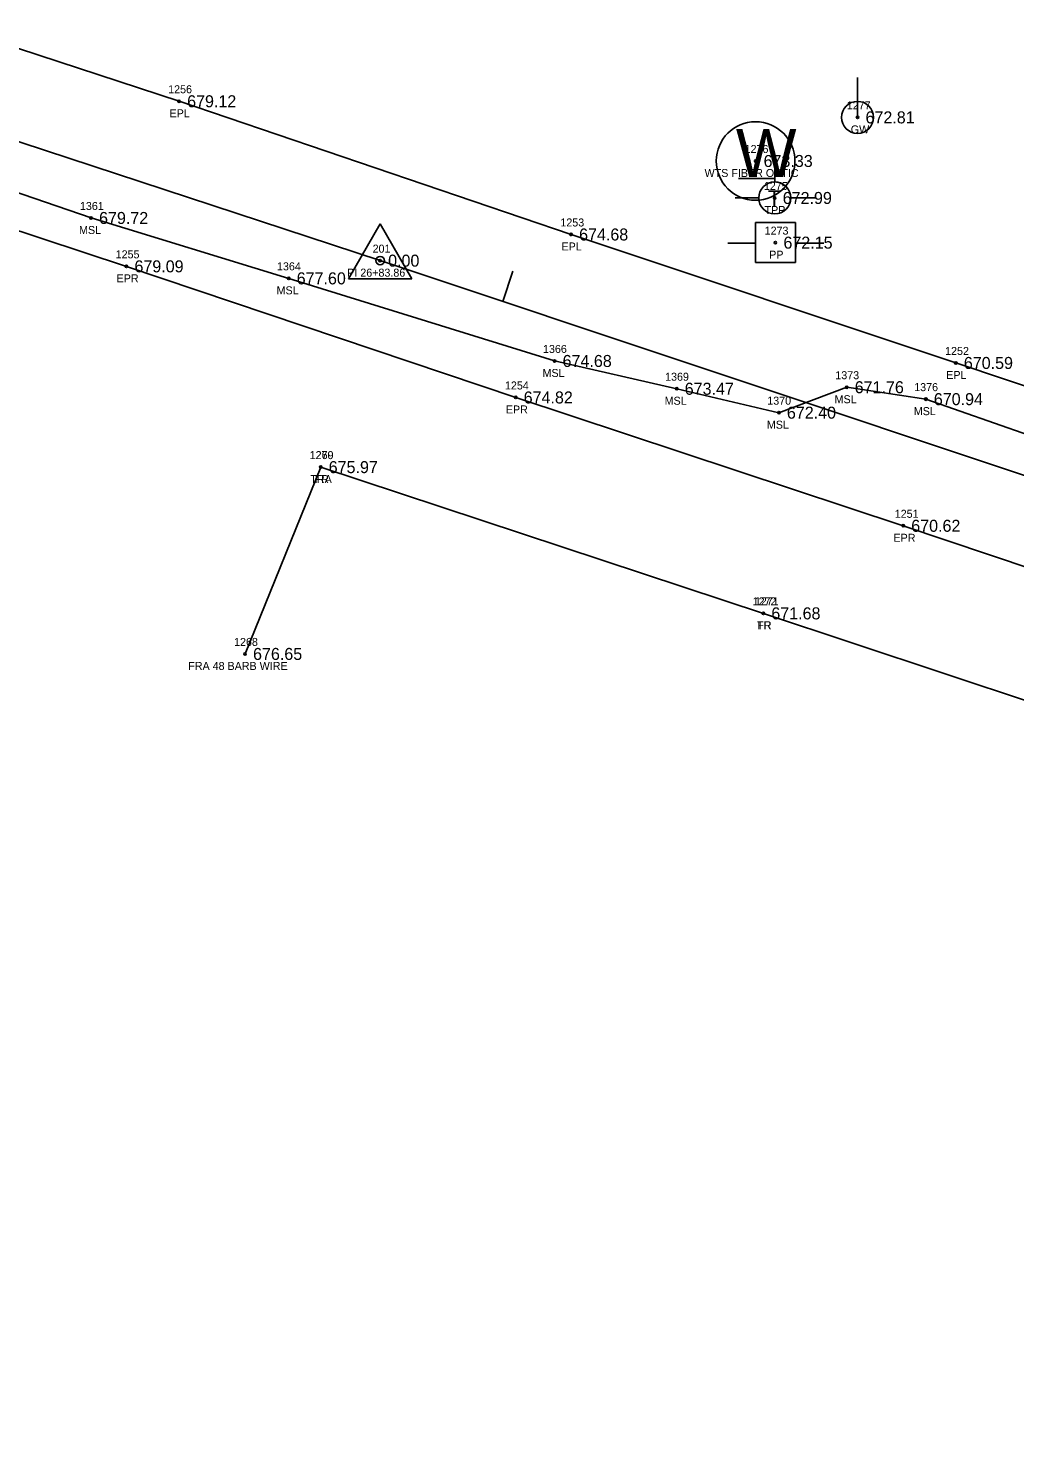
# Model space of a CAD drawing. Extents: x 1655137 to 1657928, y 1003994 to 1005407.
# Drawn here: x 1656025.3 to 1656148.5, y 1004580.8 to 1004755.9 of the extents above; entities that cross this region are included whole.
import ezdxf

# ---------------------------------------------------------------- set-up
doc = ezdxf.new("R2010")
doc.units = 0
for name, color, linetype in [('RD_EX_Fence_Other', 7, 'Continuous'), ('RD_EX_Fence_Other_txCode', 7, 'Continuous'), ('RD_EX_Misc', 7, 'Continuous'), ('RD_EX_Misc_txCode', 7, 'Continuous'), ('RD_EX_Road', 7, 'Continuous'), ('RD_EX_Road_txCode', 7, 'Continuous'), ('RD_EX_TX_Fence_Other_ELEV', 7, 'Continuous'), ('RD_EX_TX_Misc_ELEV', 7, 'Continuous'), ('RD_EX_TX_Road_ELEV', 7, 'Continuous'), ('RD_EX_TX_UT_ELEV', 7, 'Continuous'), ('RD_EX_TX_VEG_ELEV', 7, 'Continuous'), ('RD_EX_UT', 7, 'Continuous'), ('RD_EX_UT_txCode', 7, 'Continuous'), ('RD_EX_VEG', 7, 'Continuous'), ('RD_EX_VEG_txCode', 7, 'Continuous'), ('RD_HC_Cl', 7, 'Continuous'), ('RD_HC_Data', 7, 'Continuous'), ('RD_HC_Data_Tic', 7, 'Continuous'), ('RD_HC_Survey_ELEV', 7, 'Continuous'), ('RD_HC_txCode', 7, 'Continuous'), ('RD_SMD_Locator', 7, 'Continuous')]:
    doc.layers.add(name, color=color, linetype=linetype)

msp = doc.modelspace()

# ---------------------------------------------------------------- linework, layer by layer
at = {"layer": 'RD_EX_Fence_Other'}
msp.add_lwpolyline([(1656052.39, 1004677.71), (1656061.84, 1004701.05), (1656117.12, 1004682.78), (1656207.41, 1004652.79), (1656216.44, 1004637.08), (1656207.49, 1004611.28)], dxfattribs=at)
at = {"layer": 'RD_EX_Misc'}
msp.add_lwpolyline([(1655875.57, 1004783.81), (1655899.12, 1004775.73), (1655924.14, 1004767.92), (1655957.49, 1004756.44), (1655982.24, 1004748.48), (1656011.78, 1004739.5), (1656033.16, 1004732.17), (1656057.84, 1004724.63), (1656091.05, 1004714.31), (1656106.3, 1004710.84), (1656119.06, 1004707.85), (1656127.53, 1004711.03), (1656137.41, 1004709.54), (1656150.27, 1004705.03), (1656164.33, 1004699.6), (1656171.58, 1004694.85), (1656180.97, 1004693.87), (1656197.98, 1004688.49), (1656215.11, 1004682.58), (1656240.68, 1004675.39), (1656271.88, 1004665.01), (1656304.44, 1004655.08)], dxfattribs=at)
at = {"layer": 'RD_EX_Road'}
for points in [[(1656365.12, 1004639.99), (1656336.04, 1004649.34), (1656302.55, 1004660.37), (1656279.15, 1004668.23), (1656240.07, 1004681.05), (1656188.23, 1004698.03), (1656166.72, 1004705.51), (1656141.16, 1004714.06), (1656093.11, 1004730.11), (1656044.16, 1004746.75), (1655996.36, 1004762.45), (1655947.2, 1004778.68), (1655899.09, 1004794.03), (1655850.62, 1004809.99), (1655801.91, 1004826.1), (1655753.09, 1004842.31), (1655704.25, 1004858.1)], [(1656358.5, 1004619.83), (1656328.78, 1004629.48), (1656280.77, 1004645.39), (1656247.66, 1004656.11), (1656244.5, 1004656.52), (1656222.03, 1004663.57), (1656217.65, 1004665.96), (1656183.42, 1004677.32), (1656134.59, 1004693.72), (1656086.19, 1004709.75), (1656037.58, 1004726.13), (1655989.57, 1004741.99), (1655940.62, 1004757.88), (1655892.37, 1004773.61), (1655843.48, 1004789.36), (1655805.73, 1004801.4), (1655779.22, 1004810.43), (1655768.8, 1004813.1), (1655744.59, 1004822.13), (1655698.83, 1004837.65)]]:
    msp.add_lwpolyline(points, dxfattribs=at)
at = {"layer": 'RD_EX_UT'}
for p, q in [((1656128.88, 1004744.74), (1656128.88, 1004749.74)), ((1656118.54, 1004739.74), (1656118.54, 1004736.67)), ((1656114.02, 1004737.09), (1656118.65, 1004737.09)), ((1656113.61, 1004734.69), (1656116.54, 1004734.69)), ((1656120.54, 1004734.69), (1656123.61, 1004734.69)), ((1656121.12, 1004731.6), (1656116.12, 1004731.6)), ((1656116.12, 1004731.6), (1656116.12, 1004726.6)), ((1656121.12, 1004726.6), (1656121.12, 1004731.6)), ((1656112.69, 1004729.03), (1656116.16, 1004729.03)), ((1656121.05, 1004729.03), (1656124.69, 1004729.03)), ((1656116.12, 1004726.6), (1656121.12, 1004726.6))]:
    msp.add_line(p, q, dxfattribs=at)
for centre, radius in [((1656128.88, 1004744.74), 2), ((1656116.15, 1004739.29), 4.91), ((1656118.54, 1004734.67), 2)]:
    msp.add_circle(centre, radius, dxfattribs=at)
at = {"layer": 'RD_EX_VEG'}
msp.add_lwpolyline([(1656061.84, 1004701.05), (1656117.12, 1004682.78), (1656207.41, 1004652.79)], dxfattribs=at)
at = {"layer": 'RD_HC_Cl'}
for p, q in [((1655701.51, 1004847.78), (1656069.26, 1004726.84)), ((1656069.26, 1004726.84), (1656507.36, 1004580.77))]:
    msp.add_line(p, q, dxfattribs=at)
at = {"layer": 'RD_HC_Data'}
for p, q in [((1656065.29, 1004724.55), (1656069.26, 1004731.43)), ((1656069.26, 1004731.43), (1656073.23, 1004724.55)), ((1656065.29, 1004724.55), (1656073.23, 1004724.55))]:
    msp.add_line(p, q, dxfattribs=at)
msp.add_circle((1656069.26, 1004726.84), 0.529, dxfattribs=at)
at = {"layer": 'RD_HC_Data_Tic'}
msp.add_line((1656084.57, 1004721.74), (1656085.84, 1004725.53), dxfattribs=at)
at = {"layer": 'RD_SMD_Locator'}
for centre in [(1656044.16, 1004746.75), (1656128.88, 1004744.74), (1656116.15, 1004739.29), (1656118.54, 1004734.67), (1656033.16, 1004732.17), (1656093.11, 1004730.11), (1656118.63, 1004729.09), (1656069.26, 1004726.84), (1656037.58, 1004726.13), (1656057.84, 1004724.63), (1656091.05, 1004714.31), (1656141.16, 1004714.06), (1656106.3, 1004710.84), (1656127.53, 1004711.03), (1656086.19, 1004709.75), (1656137.41, 1004709.54), (1656119.06, 1004707.85), (1656061.84, 1004701.05), (1656061.84, 1004701.05), (1656134.59, 1004693.72), (1656117.12, 1004682.78), (1656117.12, 1004682.78), (1656052.39, 1004677.71)]:
    msp.add_circle(centre, 0.15, dxfattribs=at)

# ---------------------------------------------------------------- texts
at = {"layer": 'RD_EX_Fence_Other_txCode'}
for s, p in [('1269', (1656060.47, 1004702.05)), ('FR', (1656061.08, 1004699.05)), ('1272', (1656115.78, 1004683.78)), ('FR', (1656116.37, 1004680.78)), ('1268', (1656051.02, 1004678.71)), ('FRA 48 BARB WIRE', (1656045.3, 1004675.71))]:
    msp.add_text(s, height=1, dxfattribs=at).set_placement(p)
at = {"layer": 'RD_EX_Misc_txCode'}
for s, p in [('1361', (1656031.77, 1004733.17)), ('MSL', (1656031.66, 1004730.17)), ('1364', (1656056.38, 1004725.63)), ('MSL', (1656056.33, 1004722.63)), ('1366', (1656089.6, 1004715.31)), ('MSL', (1656089.54, 1004712.31)), ('1369', (1656104.85, 1004711.84)), ('1373', (1656126.11, 1004712.03)), ('1376', (1656135.96, 1004710.54)), ('MSL', (1656104.79, 1004708.84)), ('1370', (1656117.61, 1004708.85)), ('MSL', (1656126.02, 1004709.03)), ('MSL', (1656135.91, 1004707.54)), ('MSL', (1656117.56, 1004705.85))]:
    msp.add_text(s, height=1, dxfattribs=at).set_placement(p)
at = {"layer": 'RD_EX_Road_txCode'}
for s, p in [('1256', (1656042.79, 1004747.75)), ('EPL', (1656042.96, 1004744.75)), ('1253', (1656091.77, 1004731.11)), ('EPL', (1656091.91, 1004728.11)), ('1255', (1656036.23, 1004727.13)), ('EPR', (1656036.35, 1004724.13)), ('1252', (1656139.82, 1004715.06)), ('EPL', (1656139.96, 1004712.06)), ('1254', (1656084.85, 1004710.75)), ('EPR', (1656084.96, 1004707.75)), ('1251', (1656133.53, 1004694.72)), ('EPR', (1656133.37, 1004691.72))]:
    msp.add_text(s, height=1, dxfattribs=at).set_placement(p)
at = {"layer": 'RD_EX_TX_Fence_Other_ELEV'}
for s, p in [('675.97', (1656062.84, 1004700.3)), ('671.68', (1656118.12, 1004682.03)), ('676.65', (1656053.39, 1004676.96))]:
    msp.add_text(s, height=1.5, dxfattribs=at).set_placement(p)
at = {"layer": 'RD_EX_TX_Misc_ELEV'}
for s, p in [('679.72', (1656034.16, 1004731.42)), ('677.60', (1656058.84, 1004723.88)), ('674.68', (1656092.05, 1004713.56)), ('673.47', (1656107.3, 1004710.09)), ('671.76', (1656128.53, 1004710.28)), ('670.94', (1656138.41, 1004708.79)), ('672.40', (1656120.06, 1004707.1))]:
    msp.add_text(s, height=1.5, dxfattribs=at).set_placement(p)
at = {"layer": 'RD_EX_TX_Road_ELEV'}
for s, p in [('679.12', (1656045.16, 1004746)), ('674.68', (1656094.11, 1004729.36)), ('679.09', (1656038.58, 1004725.38)), ('670.59', (1656142.16, 1004713.31)), ('674.82', (1656087.19, 1004709)), ('670.62', (1656135.59, 1004692.97))]:
    msp.add_text(s, height=1.5, dxfattribs=at).set_placement(p)
at = {"layer": 'RD_EX_TX_UT_ELEV'}
for s, p in [('672.81', (1656129.88, 1004743.99)), ('673.33', (1656117.15, 1004738.54)), ('672.99', (1656119.54, 1004733.92))]:
    msp.add_text(s, height=1.5, dxfattribs=at).set_placement(p)
at = {"layer": 'RD_EX_TX_VEG_ELEV'}
for s, p in [('675.97', (1656062.84, 1004700.3)), ('671.68', (1656118.12, 1004682.03))]:
    msp.add_text(s, height=1.5, dxfattribs=at).set_placement(p)
at = {"layer": 'RD_EX_UT'}
for s, height, p in [('W', 6, (1656113.69, 1004737.29)), ('T', 2, (1656117.69, 1004733.62))]:
    msp.add_text(s, height=height, dxfattribs=at).set_placement(p)
at = {"layer": 'RD_EX_UT_txCode'}
for s, p in [('1277', (1656127.54, 1004745.74)), ('GW', (1656128.04, 1004742.74)), ('1276', (1656114.78, 1004740.29)), ('WTS FIBER OPTIC', (1656109.78, 1004737.29)), ('1275', (1656117.19, 1004735.67)), ('TPP', (1656117.27, 1004732.67)), ('1273', (1656117.28, 1004730.09)), ('PP', (1656117.85, 1004727.09))]:
    msp.add_text(s, height=1, dxfattribs=at).set_placement(p)
at = {"layer": 'RD_EX_VEG_txCode'}
for s, p in [('1270', (1656060.45, 1004702.05)), ('TRA', (1656060.55, 1004699.05)), ('1271', (1656116.06, 1004683.78)), ('TR', (1656116.33, 1004680.78))]:
    msp.add_text(s, height=1, dxfattribs=at).set_placement(p)
at = {"layer": 'RD_HC_Survey_ELEV'}
for s, p in [('672.15', (1656119.63, 1004728.34)), ('0.00', (1656070.26, 1004726.09))]:
    msp.add_text(s, height=1.5, dxfattribs=at).set_placement(p)
at = {"layer": 'RD_HC_txCode'}
for s, p in [('201', (1656068.32, 1004727.84)), ('PI 26+83.86', (1656065.15, 1004724.84))]:
    msp.add_text(s, height=1, dxfattribs=at).set_placement(p)

doc.saveas('drawing.dxf')
